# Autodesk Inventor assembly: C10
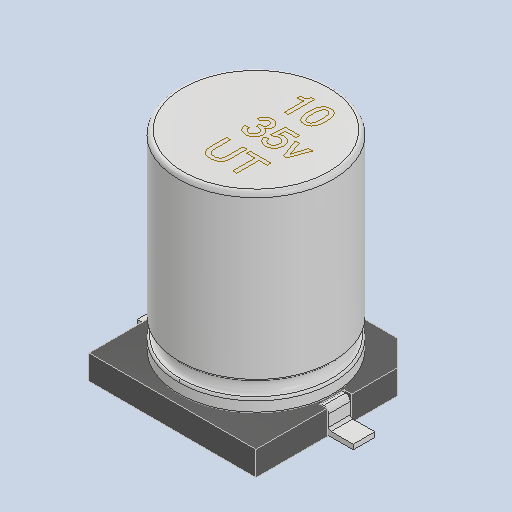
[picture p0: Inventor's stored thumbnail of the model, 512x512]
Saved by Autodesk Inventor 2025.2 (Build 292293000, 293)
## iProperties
Created: 2025-04
Part Number: C10
Description: PART--DESC
Document SubType Name: Assembly
Designer: BennF
Author: BennF
Revision Number: NONE
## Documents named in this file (4)
- C:\Users\BennF\Nextcloud\Benutzer\CNC JarBeRi\existing parts\Electronics\RepRap A4988 Shied (USE WITHOUT ARDUINO)\reprap-a4988-1.snapshot.1\RepRap\RepRap\C10.iam
- C:\Users\BennF\Nextcloud\Benutzer\CNC JarBeRi\existing parts\Electronics\RepRap A4988 Shied (USE WITHOUT ARDUINO)\reprap-a4988-1.snapshot.1\RepRap\RepRap\C10 Geometry.ipt
- C:\Users\BennF\Nextcloud\Benutzer\CNC JarBeRi\existing parts\Electronics\RepRap A4988 Shied (USE WITHOUT ARDUINO)\reprap-a4988-1.snapshot.1\RepRap\RepRap\bay2.iam
- C:\Users\BennF\Nextcloud\Benutzer\CNC JarBeRi\existing parts\Electronics\RepRap A4988 Shied (USE WITHOUT ARDUINO)\reprap-a4988-1.snapshot.1\RepRap\RepRap\name4.ipt
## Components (3 placed, 3 different names)
1. C10 Geometry
2. bay2 [sub-assembly]
3. name4
